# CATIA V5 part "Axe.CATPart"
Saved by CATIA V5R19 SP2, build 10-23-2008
Part number: Axe
Publications: "Dav"
Bounding box of the stored display mesh (mm): x 0 to 290, y -13 to 13, z -12.99 to 12.99
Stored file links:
  C:\Users\Vianney\Documents\Garantie\Cours\2A\IAO\IAO-proj-Catia\Axe.CATPart
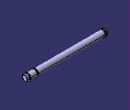
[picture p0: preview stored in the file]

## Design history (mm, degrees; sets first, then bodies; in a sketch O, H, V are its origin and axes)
Parameters
  Dav = 20 mm
  Laxev = 290 mm
Body1 (main body)
  Sketch1 on yz-plane, origin (0, 0, 0), H (0, 1, 0), V (0, 0, 1)
    circle A1 centre (0, 0) radius 10
    radius A1 = 10 {= Dav /2}
  Pad1: profile Sketch1, direction (1, 0, 0), length 290 {= Laxev}
  Fillet1: radius 2, on edge [face of Pad1 from Sketch1.A1 | end face of Pad1]; edge [start face of Pad1 | face of Pad1 from Sketch1.A1]
  Plane1: type Offset, RefPlane end face of Pad1, Offset 8
  Plane2: type Offset, RefPlane start face of Pad1, Offset 8
  Sketch2 on Plane1, origin (282, 0, 0), H (0, -1, 0), V (0, 0, 1)
    circle A1 centre (0, 0) radius 13
    radius A1 = 13 {= Dav /2+3mm}
  Pad2: profile Sketch2, direction (-1, 0, 0), length 2
  Sketch3 on Plane2, origin (8, 0, 0), H (0, 1, 0), V (0, 0, 1)
    circle A1 centre (0, 0) radius 13
    radius A1 = 13 {= Dav /2+3mm}
  Pad3: profile Sketch3, direction (1, 0, 0), length 2
  Plane3: type Offset, RefPlane end face of Pad1, Offset 35
  Sketch4 on Plane3, origin (255, 0, 0), H (0, -1, 0), V (0, 0, 1)
    circle A1 centre (0, 0) radius 13
    radius A1 = 13 {= Dav /2+3mm}
  Pad4: profile Sketch4, direction (-1, 0, 0), length 2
